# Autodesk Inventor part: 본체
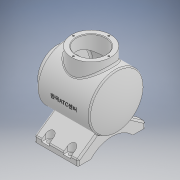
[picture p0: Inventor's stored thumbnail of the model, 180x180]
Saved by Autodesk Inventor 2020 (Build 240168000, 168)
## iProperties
Created: 2023-12
Part Number: 본체
Material: 일반
Document SubType Name: Modeling
Designer: 1강의실14
Density: 1 g/cm^3
Appearance: 기본값
Author: 1강의실14
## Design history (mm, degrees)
sketch "스케치1"
  geometry: L1 (-22.6, 0)-(135.6, 0) reference; L2 (113, 0)-(5, 0); L3 (5, 0)-(5, 50); L4 (5, 50)-(101.336, 50); A1 r 113 centre (0, 0) between (75.035, -84.491) and (75.035, 84.491); 2 further points
  constraints: 6 end point, 4 point on circle, 2 coincident, 2 horizontal, 1 centre point, 1 point on line, 1 vertical
  dimensions: "d0" = 113 radius of A1; "d1" = 108 distance of L2.start L2.end; "d2" = 50 distance of L2.end L3.end
revolve "회전1" sketch "스케치1" stored, may be unused: angle "d3" = 90 deg
sketch "스케치2"
  geometry: 1 further point
fillet "모깎기1" dims "d5" = 3
feature "쉘2" dims "d6" = 7
sketch "스케치3"
  geometry: C1 r 36 at (0, 0); 1 further point
  constraints: 1 centre point, 1 coincident
  dimensions: "d7" = 72 diameter of C1
extrude "돌출1" join sketch "스케치3" distance "d8" = 12; taper "d9" = 0 deg
sketch "스케치4"
  geometry: C1 r 36 at (0, 0) reference; 2 further points
  constraints: 1 coincident
hole "구멍1" sketch "스케치4" at (0, 0) diameter "d10" = 54; stored, may be unused: countersink angle "d14" = 90 deg, drill point angle "d16" = 0 deg; dims "d11" = 6, "d12" = 4, "d13" = 2, "d15" = 19
node "작업 평면1"
sketch "스케치5"
  geometry: L1 (7, -36)-(7, 36) reference; L2 (7, 0)-(-55, 0); C1 r 36 at (-55, 0); 1 further point
  constraints: 2 end point, 1 centre point, 1 coincident, 1 horizontal, 1 midpoint
  dimensions: "d18" = 62 distance of L2.start L2.end; "d19" = 72 diameter of C1
extrude "돌출2" join sketch "스케치5" stored distance "d20" = 12; taper "d21" = 0 deg
node "작업 평면2"
sketch "스케치7"
  geometry: L1 (0, 0)-(-77, 0); L2 (-77, 0)-(-77, 62); L3 (-77, 62)-(-67, 62); L4 (-67, 62)-(-23.587, 0); L5 (-77, 0)-(-77, 38.5); L6 (-77, 0)-(-60, 0); L7 (-60, 0)-(-60, 38.5); L8 (-60, 38.5)-(-77, 38.5); L9 (-77, 0)-(-77, -38.5); L10 (-77, -38.5)-(-60, -38.5); L11 (-60, -38.5)-(-60, 0); C1 r 43 at (0, 0) reference; C2 r 50 at (0, 0) reference; A1 r 52.096 centre (-112.096, 0) between (-77, -38.5) and (-77, 38.5); 2 further points
  constraints: 22 end point, 4 perpendicular, 4 point on line, 3 point on circle, 1 centre point, 1 horizontal, 1 vertical
  dimensions: "d31" = 77 distance of L1.start L1.end; "d32" = 62 distance of L1.end L2.end; "d33" = 10 distance of L2.end L3.end; "d34" = 55 deg angle of L3 L4; "d35" = 38.5 distance of L1.end L5.end; "d36" = 17 distance of L1.end L6.end; "d37" = 38.5 distance of L1.end L9.end; "d38" = 17 distance of L9.end L10.end
extrude "돌출3" join sketch "스케치7" distance "d39" = 80; taper "d40" = 0 deg
sketch "스케치8"
  geometry: C1 r 36 at (0, 0) reference; 2 further points
  constraints: 1 coincident
hole "구멍2" sketch "스케치8" at (0, 0) diameter "d41" = 54; stored, may be unused: countersink angle "d45" = 90 deg, drill point angle "d47" = 0 deg; dims "d42" = 6, "d43" = 4, "d44" = 2, "d46" = 40
sketch "스케치10"
  geometry: 1 further point
node "작업 평면3"
sketch "스케치11"
  geometry: L1 (-13, 62)-(-93, 62) reference; L2 (-93, 62)-(-93, 54); L3 (-93, 62)-(-73, 62); L4 (-73, 62)-(-73, 54); L5 (-80, 54)-(-80, 75.736); L6 (-66, 54)-(-66, 75.736); L7 (-66, 75.736)-(-80, 75.736); A1 r 7 centre (-73, 54) between (-80, 54) and (-66, 54); 5 further points; 2 other entities
  constraints: 12 end point, 2 point on circle, 2 tangent, 2 vertical, 1 centre point, 1 coincident, 1 horizontal, 1 perpendicular, 1 point on line, 3 other
  dimensions: "d59" = 8 distance of L1.end L2.end; "d60" = 20 distance of L1.end L3.end; "d61" = 8 distance of L3.end L4.end; "d62" = 14 diameter of A1; "d63" = 21.7361 distance of L6.start L6.end
extrude "돌출4" cut sketch "스케치11" distance "d64" = 16; taper "d65" = 0 deg
sketch "스케치12"
  geometry: A1 r 7 centre (73, -54) between (80, -54) and (66, -54) reference; 2 further points
  constraints: 1 coincident
hole "구멍3" sketch "스케치12" at (73, -54) diameter "d66" = 9; stored, may be unused: countersink angle "d70" = 90 deg, drill point angle "d72" = 0 deg; dims "d67" = 6, "d68" = 4, "d69" = 2, "d71" = 6
fillet "모깎기5" dims "d82" = 3
sketch "스케치13"
  geometry: L1 (0, 0)-(0, 32.5)
  constraints: 2 end point, 1 vertical
  dimensions: "d83" = 32.5 distance of L1.start L1.end
hole "구멍4" sketch "스케치13" at (0, 32.5) diameter "d84" = 3.242; stored, may be unused: countersink angle "d88" = 90 deg, drill point angle "d90" = 118 deg; dims "d85" = 8, "d86" = 4, "d87" = 2, "d89" = 10
sketch "스케치14"
  geometry: L1 (0, 0)-(0, 32.5); C1 r 36 at (0, 0) reference; 1 further point
  constraints: 2 end point, 1 vertical
  dimensions: "d95" = 32.5 distance of L1.start L1.end
hole "구멍5" sketch "스케치14" at (0, 32.5) diameter "d96" = 3.242; stored, may be unused: countersink angle "d100" = 90 deg, drill point angle "d102" = 118 deg; dims "d97" = 8, "d98" = 4, "d99" = 2, "d101" = 10
fillet "모깎기6" dims "d106" = 3
fillet "모깎기9" dims "d109" = 3
fillet "모깎기10" dims "d110" = 3
fillet "모깎기11" dims "d111" = 3
fillet "모깎기12" dims "d112" = 3
fillet "모깎기13" dims "d113" = 3
fillet "모깎기14" dims "d114" = 3
node "작업 평면4"
sketch "스케치15"
  geometry: L1 (-7, 36)-(-7, -36) reference; L2 (113, 0)-(0, 0); A1 r 113 centre (0, 0) between (102.166, -48.282) and (102.166, 48.282) reference; 1 further point
  constraints: 2 end point, 1 horizontal, 1 point on circle, 1 point on line, 1 other
  dimensions: "d116" = 62 distance from line of L1 point (55, 0)
feature "엠보싱1" sketch "스케치15" dims "d7" = 72, "d117" = 0.5, "d118" = 0
fillet "모깎기18" dims "d122" = 3
fillet "모깎기19" dims "d123" = 3
chamfer "모따기1" distance "d124" = 1; stored, may be unused: second distance "d125" = 2, angle "d126" = 45 deg
feature "분할1"
node "솔리드1"
mirror "미러1"
pattern_linear "직사각형 패턴1" dims "d75" = 40
mirror "미러2"
pattern_linear "직사각형 패턴2" dims "d78" = 40
pattern_circular "원형 패턴1" dims angle "d92" = 360 deg
pattern_circular "원형 패턴2" dims angle "d104" = 360 deg
feature "A9D066F2-1C7D-4E18-AEED-F7BC21143FA4" dims "d10" = 54, "d11" = 6, "d12" = 4, "d13" = 2, "d14" = 90 deg, "d15" = 19, "d16" = 0
other parameters: "d17" = 65, "d27" = 13, "d57" = -55, "d115" = 65
